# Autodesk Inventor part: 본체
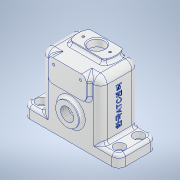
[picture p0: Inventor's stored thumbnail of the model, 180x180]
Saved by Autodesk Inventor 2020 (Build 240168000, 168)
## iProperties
Created: 2023-12
Part Number: 본체
Material: 알루미늄 6061
Document SubType Name: Modeling
Designer: oem
Density: 2.7 g/cm^3
Appearance: 알루미늄 - 평지
Mass: 217.508 g
Surface Area: 364.403 cm^2
Volume: 80.5585 cm^3
Author: oem
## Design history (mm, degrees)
sketch "스케치1"
  geometry: L1 (50, -40)-(-50, -40); L2 (-50, -40)-(-50, 0); L3 (-50, 0)-(50, 0); L4 (50, 0)-(50, -40); 2 further points
  constraints: 8 end point, 2 coincident, 2 parallel, 1 horizontal, 1 midpoint, 1 perpendicular
  dimensions: "d0" = 100 distance of L2.end L3.end; "d1" = 40 distance of L1.end L2.end
extrude "돌출1" new body sketch "스케치1" distance "d2" = 12; taper "d3" = 0 deg
sketch "스케치2"
  geometry: L1 (-50, 0)-(50, 0) reference; L2 (50, 40)-(-50, 40) reference; L3 (-31, 40)-(31, 40); L4 (31, 40)-(31, 0); L5 (31, 0)-(-31, 0); L6 (-31, 0)-(-31, 40); 6 further points
  constraints: 8 end point, 2 midpoint, 2 parallel, 1 coincident, 1 collinear, 1 horizontal, 1 perpendicular, 1 point on line
  dimensions: "d4" = 62 distance between parallel lines of L4 L6
extrude "돌출2" join sketch "스케치2" distance "d5" = 60; taper "d6" = 0 deg
sketch "스케치3"
  geometry: L1 (0, 0)-(100, 0) reference; C1 r 12 at (50, 28); 2 further points
  constraints: 1 centre point, 1 midpoint, 1 vertical alignment
  dimensions: "d7" = 24 diameter of C1; "d8" = 28 distance of C1.centre point (50, 0)
extrude "돌출3" join sketch "스케치3" distance "d9" = 4; taper "d10" = 0 deg
sketch "스케치4"
  geometry: L1 (0, 0)-(100, 0) reference; L2 (19, 72)-(81, 72) reference; L3 (30, 72)-(70, 72); L4 (70, 72)-(70, 48); L5 (70, 48)-(30, 48); L6 (30, 48)-(30, 72); 4 further points
  constraints: 8 end point, 2 midpoint, 2 parallel, 1 horizontal, 1 perpendicular, 1 point on line, 1 vertical alignment
  dimensions: "d11" = 40 distance between parallel lines of L4 L6; "d12" = 24 distance between parallel lines of L5 L2
extrude "돌출4" join sketch "스케치4" distance "d13" = 4; taper "d14" = 0 deg
sketch "스케치5"
  geometry: C1 r 12 at (50, 28) reference; C2 r 20 at (50, 28); 1 further point
  constraints: 1 centre point, 1 coincident
  dimensions: "d15" = 40 diameter of C2
extrude "돌출5" join sketch "스케치5" distance "d16" = 4; taper "d17" = 0 deg
sketch "스케치6"
  geometry: L1 (20, -4)-(-20, -4) reference; L2 (-17.321, 37)-(17.321, 37); L3 (-17.321, 17)-(17.321, 17); A1 r 20 centre (0, 27) between (-17.321, 37) and (17.321, 37); 1 further point
  constraints: 4 end point, 4 point on circle, 1 centre point, 1 horizontal, 1 vertical alignment
  dimensions: "d18" = 40 diameter of A1; "d19" = 31 distance from line of A1.centre L1; "d20" = 20 distance between parallel lines of L3 L2; "d21" = 10 distance from line of L2 A1.centre
extrude "돌출6" join sketch "스케치6" distance "d22" = 4; taper "d23" = 0 deg
sketch "스케치7"
  geometry: L1 (31, 0)-(50, 0) reference; 6 further points
  constraints: 2 horizontal alignment, 2 vertical alignment
  dimensions: "d27" = 82 distance of point (41, 30) point (-41, 30); "d28" = 20 distance of point (41, 30) point (41, 10); "d29" = 10 distance from line of point (41, 10) L1; "d30" = 41 horizontal distance of point (41, 30) point (0, 0)
hole "구멍1" sketch "스케치7" at (41, 30), (41, 10), (-41, 30), (-41, 10) diameter "d31" = 6.6; stored, may be unused: countersink angle "d35" = 90 deg, drill point angle "d37" = 118 deg; dims "d32" = 10, "d33" = 11, "d34" = 6.6, "d36" = 15
sketch "스케치8"
  geometry: C1 r 12 at (0, 0) reference; 2 further points
  constraints: 1 coincident
hole "구멍2" sketch "스케치8" at (0, 0) diameter "d38" = 13.835; stored, may be unused: countersink angle "d42" = 90 deg, drill point angle "d44" = 118 deg; dims "d39" = 8, "d40" = 11, "d41" = 6.6, "d43" = 8
sketch "스케치9"
  geometry: C1 r 20 at (0, 0) reference; C2 r 9 at (0, 0); 1 further point
  constraints: 1 centre point, 1 coincident
  dimensions: "d45" = 18 diameter of C2
extrude "돌출7" cut sketch "스케치9" distance "d46" = 8; taper "d47" = 0 deg
sketch "스케치10"
  geometry: L1 (50, 0)-(50, -40) reference; L2 (-50, 0)-(50, 0) reference; L3 (-27, -4)-(27, -4); L4 (27, -4)-(27, -36); L5 (27, -36)-(-27, -36); L6 (-27, -36)-(-27, -4); 9 further points
  constraints: 8 end point, 4 midpoint, 2 parallel, 1 horizontal, 1 horizontal alignment, 1 perpendicular, 1 vertical alignment
  dimensions: "d48" = 32 distance between parallel lines of L5 L3; "d49" = 54 distance between parallel lines of L4 L6
extrude "돌출8" cut sketch "스케치10" distance "d50" = 68; taper "d51" = 0 deg
sketch "스케치11"
  geometry: C1 r 8 at (0, 27); A1 r 20 centre (0, 27) between (17.321, 17) and (17.321, 37) reference; 1 further point
  constraints: 1 centre point, 1 coincident
  dimensions: "d52" = 16 diameter of C1
extrude "돌출9" cut sketch "스케치11" distance "d53" = 68; taper "d54" = 0 deg
sketch "스케치12"
  geometry: C1 r 9 at (0, 0) reference; C2 r 20 at (0, 0) reference; A1 r 15 centre (0, 0) between (0, 15) and (-15, 0); 3 further points
  constraints: 4 point on circle, 2 horizontal alignment, 2 vertical alignment, 1 centre point, 1 coincident
  dimensions: "d55" = 30 diameter of A1
hole "구멍3" sketch "스케치12" at (0, 15), (-15, 0), (0, -15), (15, 0) diameter "d56" = 2.459; stored, may be unused: countersink angle "d60" = 90 deg, drill point angle "d62" = 118 deg; dims "d57" = 9, "d58" = 11, "d59" = 6.6, "d61" = 9
sketch "스케치13"
  geometry: L1 (70, 72)-(30, 72) reference; 5 further points
  constraints: 1 horizontal alignment
  dimensions: "d63" = 28 distance of point (64, 66) point (36, 66); "d64" = 14 horizontal distance of point (50, 0) point (64, 66); "d65" = 6 distance from line of point (64, 66) L1
hole "구멍4" sketch "스케치13" at (36, 66), (64, 66) diameter "d66" = 2.459; stored, may be unused: countersink angle "d70" = 90 deg, drill point angle "d72" = 118 deg; dims "d67" = 9, "d68" = 11, "d69" = 6.6, "d71" = 9
sketch "스케치14"
  geometry: L1 (20, -4)-(15, -4) reference; C1 r 8 at (0, 27) reference; 3 further points
  constraints: 1 horizontal alignment
  dimensions: "d73" = 28 distance of point (14, 27) point (-14, 27); "d74" = 14 distance of point (-14, 27) C1.centre; "d75" = 31 distance from line of point (14, 27) L1
hole "구멍5" sketch "스케치14" at (-14, 27), (14, 27) diameter "d76" = 2.459; stored, may be unused: countersink angle "d80" = 90 deg, drill point angle "d82" = 118 deg; dims "d77" = 9, "d78" = 11, "d79" = 6.6, "d81" = 9
node "작업 평면1"
sketch "스케치15"
  geometry: L1 (-4, 28)-(-4, 4) reference; L2 (4, -12)-(36, -12) reference; 2 further points
  constraints: 1 other
  dimensions: "d84" = 23 distance from line of point (19, 28) L1; "d85" = 40 distance from line of point (19, 28) L2
feature "엠보싱1" sketch "스케치15" dims "d0" = 100, "d1" = 40, "d86" = 0.5, "d87" = 0
fillet "모깎기12" dims "d96" = 7
fillet "모깎기14" dims "d98" = 3
fillet "모깎기16" dims "d100" = 7
fillet "모깎기17" dims "d101" = 3
fillet "모깎기19" dims "d103" = 3
chamfer "모따기1" distance "d105" = 1; stored, may be unused: second distance "d106" = 2, angle "d107" = 45 deg
fillet "모깎기21" dims "d108" = 3
fillet "모깎기22" dims "d109" = 5
fillet "모깎기23" dims "d110" = 3
chamfer "모따기2" distance "d111" = 1; stored, may be unused: second distance "d112" = 2, angle "d113" = 45 deg
fillet "모깎기25" dims "d115" = 3
fillet "모깎기27" dims "d117" = 7
fillet "모깎기28" dims "d118" = 3
node "솔리드1"
feature "A9D066F2-1C7D-4E18-AEED-F7BC21143FA4" dims "d31" = 6.6, "d32" = 10, "d33" = 11, "d34" = 6.6, "d35" = 90 deg, "d36" = 15, "d37" = 118 deg
other parameters: "d83" = 5
